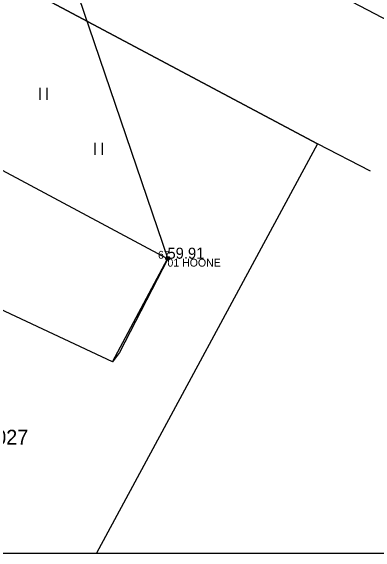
# Model space of a CAD drawing. Extents: x 640891 to 641083, y 6456526 to 6456669.
# Drawn here: x 640970.21 to 640993.38, y 6456525.87 to 6456560.25 of the extents above; entities that cross this region are included whole.
import ezdxf

# ---------------------------------------------------------------- set-up
doc = ezdxf.new("R2010")
doc.units = 0
for name, color, linetype in [('100koma2', 7, 'Continuous'), ('HALJASTUS', 7, 'Continuous'), ('HOONE', 7, 'Continuous'), ('MOOTKORG', 7, 'Continuous'), ('MOOTMPUNKT', 7, 'Continuous'), ('MOOTNR', 7, 'Continuous'), ('MOOTPIIR', 7, 'Continuous'), ('PIIR', 7, 'Continuous'), ('VORMISTUS', 7, 'Continuous')]:
    doc.layers.add(name, color=color, linetype=linetype)

msp = doc.modelspace()

# ---------------------------------------------------------------- linework, layer by layer
at = {"layer": 'HALJASTUS'}
for p, q in [((640972.045, 6456555.381), (640972.045, 6456554.619)), ((640972.5, 6456555.381), (640972.5, 6456554.619)), ((640975.545, 6456551.881), (640975.545, 6456551.119)), ((640976, 6456551.881), (640976, 6456551.119))]:
    msp.add_line(p, q, dxfattribs=at)
at = {"layer": 'HOONE'}
for p, q in [((640980.143, 6456544.534), (640963.241, 6456553.549)), ((640976.662, 6456538.007), (640980.143, 6456544.534))]:
    msp.add_line(p, q, dxfattribs=at)
at = {"layer": 'MOOTMPUNKT'}
msp.add_circle((640980.143, 6456544.534), 0.1, dxfattribs=at)
at = {"layer": 'MOOTPIIR'}
msp.add_lwpolyline([(640994.744, 6456619.938), (640993.953, 6456602.696), (640993.953, 6456601.05), (640978.828, 6456568.525), (640974.506, 6456561.178), (640980.174, 6456544.523), (640977.11, 6456538.585), (640976.662, 6456538.007), (640959.29, 6456546.142)], dxfattribs=at)
at = {"layer": 'PIIR'}
for points in [[(640890.598, 6456615.08), (640904.36, 6456607.7), (640930.79, 6456593.51), (640957.22, 6456579.32), (640983.63, 6456565.13), (641002.905, 6456555.058)], [(640993.023, 6456550.09), (640989.66, 6456551.83), (640963.18, 6456565.91), (640936.74, 6456580.1), (640910.31, 6456594.28), (640890.598, 6456604.875)], [(640941.583, 6456525.865), (640963.18, 6456565.91), (640989.66, 6456551.83), (640975.643, 6456525.865)]]:
    msp.add_lwpolyline(points, dxfattribs=at)
at = {"layer": 'VORMISTUS'}
msp.add_line((640890.598, 6456525.865), (641082.733, 6456525.865), dxfattribs=at)

# ---------------------------------------------------------------- texts
at = {"layer": '100koma2'}
msp.add_text('01 HOONE', height=0.5, dxfattribs=at).set_placement((640980.143, 6456544.034))
at = {"layer": 'MOOTKORG'}
msp.add_text('59.91', height=0.7, dxfattribs=at).set_placement((640980.143, 6456544.534))
at = {"layer": 'MOOTNR'}
msp.add_text('67', height=0.5, dxfattribs=at).set_placement((640979.543, 6456544.534))
at = {"layer": 'PIIR'}
msp.add_text('17001:002:0027', height=0.9375, dxfattribs=at).set_placement((640962.25, 6456532.75))

doc.saveas('drawing.dxf')
